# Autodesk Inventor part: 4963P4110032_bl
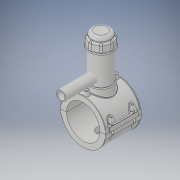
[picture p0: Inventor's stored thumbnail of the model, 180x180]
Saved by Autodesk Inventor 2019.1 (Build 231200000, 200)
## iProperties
Created: 2017-07
Part Number: 4963P4110032_bl
Material: Generic
Document SubType Name: Modeling
Designer: KIM
Density: 1 g/cm^3
Appearance: Default
Author: KIM
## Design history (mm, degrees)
derived "4963P4.ipt"
feature "Solid1::4963P4.ipt" dims "ScaleForDerivedMember" = 10
feature "Solid2::4963P4.ipt" dims "ScaleForDerivedMember" = 10
feature "Solid3::4963P4.ipt" dims "ScaleForDerivedMember" = 10
tag "TaggingFeature1"
body "Solid1"
body "Solid2"
body "Solid3"
other parameters: "d2" = 148 [user parameter], "d3" = 27.5 [user parameter], "d4" = 118 [user parameter], "d5" = 0 [user parameter], "d6" = 0.1 [user parameter], "d8" = 0 [user parameter], "d19" = 6 [user parameter], "d20" = 6 [user parameter], "d21" = 70.8 [user parameter], "d23" = 0 [user parameter], "d24" = 35.4 [user parameter], "d26" = 0 [user parameter], "d27" = 3 [user parameter], "d28" = 3 [user parameter], "d29" = 3 [user parameter], "d30" = 36.66667 [user parameter], "d31" = 6 [user parameter], "d32" = 0 [user parameter], "d33" = 0 [user parameter], "d34" = 0.6 [user parameter], "d40" = 74.36 [user parameter], "d41" = 77 [user parameter], "d43" = 0 [user parameter], "d45" = 0 [user parameter], "d47" = 142.3 [user parameter], "d70" = 15 [user parameter], "d72" = 0 [user parameter], "d73" = 6 [user parameter], "d75" = 5 [user parameter], "d76" = 0 [user parameter], "d77" = 5.5 [user parameter], "d78" = 85 [user parameter], "d79" = 15 [user parameter], "d80" = 47.2 [user parameter], "d82" = 5 deg [user parameter], "d84" = 4 [user parameter], "d85" = 14 [user parameter], "d86" = 0 [user parameter], "d87" = 3 [user parameter], "d88" = 0 [user parameter], "d89" = 1 [user parameter], "d90" = 1 [user parameter], "d91" = 94.4 [user parameter], "d92" = 0 [user parameter], "d93" = 0.5 [user parameter], "d94" = 57.89474 [user parameter], "d96" = 145.86 [user parameter], "d97" = 2.36 [user parameter], "d98" = 0 [user parameter], "d102" = 1.1 [user parameter], "d120" = 140 deg [user parameter], "d121" = 24.228 [user parameter], "d122" = 20 deg [user parameter], "d123" = 286 [user parameter], "d124" = 85.8 [user parameter], "d126" = 0 [user parameter], "d143" = 113.3 [user parameter], "d145" = 25.38462 [user parameter], "d149" = 1.65 [user parameter], "d150" = 27.92308 [user parameter], "d153" = 118 [user parameter], "d154" = 0 [user parameter], "d156" = 71.5 [user parameter], "d157" = 160 deg [user parameter], "d159" = 6.6 [user parameter], "d161" = 1.65 [user parameter], "d162" = 70.8 [user parameter], "d163" = 0 [user parameter], "d164" = 55 [user parameter], "d167" = 11 [user parameter], "d168" = 69.7561 [user parameter], "d170" = 3.75 [user parameter], "d172" = 0 [user parameter], "d173" = 1 [user parameter], "d175" = 55 [user parameter], "d176" = 20 deg [user parameter], "d177" = 7.7 [user parameter], "d178" = 33 [user parameter], "d180" = 0 [user parameter], "d183" = 13.2 [user parameter], "d184" = 6.16 [user parameter], "d185" = 38.35 [user parameter], "d186" = 38.35 [user parameter], "d187" = 71.5 [user parameter], "d188" = 9.9 [user parameter], "d189" = 7.7 [user parameter], "d190" = 0 [user parameter], "d191" = 107.25 [user parameter], "d193" = 8 [user parameter], "d194" = 4.13 [user parameter], "d195" = 90 deg [user parameter], "d197" = 0 [user parameter], "d199" = 0 [user parameter], "d200" = 16.5 [user parameter], "d202" = 0 [user parameter], "d203" = 177 [user parameter], "d204" = 73.15 [user parameter], "d205" = 53.9 [user parameter], "d206" = 65.45 [user parameter], "d207" = 132.75 [user parameter], "d208" = 138.06 [user parameter], "d209" = 164.61 [user parameter], "d210" = 66.22 [user parameter], "d211" = 77 [user parameter], "d212" = 61.6 [user parameter], "d213" = 36 [user parameter], "d216" = 0 [user parameter], "d217" = 11 [user parameter], "d218" = 11 [user parameter], "d219" = 2.2 [user parameter], "d224" = 0 [user parameter], "d225" = 56 [user parameter], "d226" = 32 [user parameter], "d227" = 25.6 [user parameter], "d228" = 132 [user parameter], "d230" = 6.6 [user parameter], "B_" = 148 [user parameter], "L_" = 118 [user parameter], "d_t" = 6 [user parameter], "H_2" = 177 [user parameter]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
